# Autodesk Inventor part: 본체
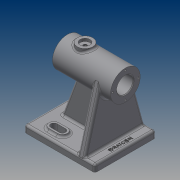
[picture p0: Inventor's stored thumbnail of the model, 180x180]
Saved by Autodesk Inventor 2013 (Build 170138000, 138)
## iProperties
Created: 2019-10
Part Number: 본체
Material: Generic
Document SubType Name: Modeling
Designer: user
Density: 1 g/cm^3
Author: user
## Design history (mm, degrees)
sketch "스케치1"
  geometry: L1 (-25, 0)-(57, 0); L2 (-25, 0)-(-25, 21); L3 (-25, 21)-(57, 21); L4 (-25, 0)-(-25, 14.5); L5 (-25, 14.5)-(37, 14.5); L6 (37, 14.5)-(37, 11.5); L7 (57, 21)-(57, 0); L8 (37, 11.5)-(57, 11.5); 1 further point
  constraints: 16 end point, 5 perpendicular, 3 point on line, 1 horizontal
  dimensions: "d0" = 82 distance of L1.start L1.end; "d1" = 25 distance of point (0, 0) L1.start; "d3" = 82 distance of L2.end L3.end; "d5" = 42 diameter of L3 L1; "d10" = 29 diameter of L5 L1; "d11" = 62 distance between parallel lines of L2 L6; "d12" = 23 diameter of L6.end L1
revolve "회전1" sketch "스케치1" stored, may be unused: angle "d13" = 90 deg
node "작업 평면1"
sketch "스케치2"
  geometry: L1 (-57, 21)-(-57, -21) reference; L2 (-57, -43)-(43, -43); L3 (43, -43)-(43, 43); L4 (43, 43)-(-57, 43); L5 (-57, 43)-(-57, -43); L6 (-57, -43)-(43, 43); L7 (43, -43)-(-57, 43); 3 further points
  constraints: 12 end point, 4 midpoint, 2 parallel, 1 horizontal, 1 perpendicular
  dimensions: "d15" = 100 distance of L4.end L3.end; "d16" = 86 distance of L3.end L2.end
extrude "돌출1" join sketch "스케치2" distance "d17" = 10; taper "d18" = 0 deg
fillet "모깎기1" dims "d19" = 3
sketch "스케치4"
  geometry: L1 (-43, 40)-(-43, -40) reference; L2 (57, -40)-(57, 40) reference; L3 (54, 43)-(-40, 43) reference; L4 (57, 0)-(42, 0); L5 (-43, 0)-(-28, 0); L6 (7, -5)-(42, -5); L7 (42, -5)-(42, 5); L8 (42, 5)-(7, 5); L9 (7, 5)-(7, -5); 1 further point
  constraints: 12 end point, 3 midpoint, 3 parallel, 1 collinear, 1 horizontal, 1 perpendicular
  dimensions: "d26" = 15 distance of L4.end L4.start; "d27" = 15 distance of L5.start L5.end; "d28" = 35 distance of L8.end L7.end; "d29" = 10 distance of L7.end L6.end
extrude "돌출3" join sketch "스케치4" stored distance "d30" = 10; taper "d31" = 0 deg
sketch "스케치5"
  geometry: L1 (37, -11.5)-(57, -11.5) reference; L2 (57, -11.5)-(57, -21) reference; L3 (57, -21)-(42, -21) reference; L4 (42, -21)-(42, -76) reference; L5 (42, -76)-(57, -76) reference; L6 (57, -76)-(57, -86) reference; L7 (57, -86)-(-43, -86) reference; L8 (-43, -86)-(-43, -76) reference; L9 (-43, -76)-(7, -76) reference; L10 (7, -76)-(7, -21) reference; L11 (7, -21)-(-25, -21) reference; L12 (-25, -21)-(-25, -14.5) reference; L13 (-25, -14.5)-(37, -14.5) reference; L14 (37, -14.5)-(37, -11.5) reference; L15 (-25, 21)-(57, 21) reference; L16 (57, 21)-(57, 11.5) reference; L17 (57, 11.5)-(37, 11.5) reference; L18 (37, 11.5)-(37, 14.5) reference; L19 (37, 14.5)-(-25, 14.5) reference; L20 (-25, 14.5)-(-25, 21) reference; L21 (-28, -76)-(-7.982, -21); 1 further point
  constraints: 2 end point, 2 point on line
  dimensions: "d32" = 15 distance of L21.start L8.end; "d33" = 70 deg angle of L9 L21
feature "리브1" sketch "스케치5" dims "d34" = 1, "d35" = 10, "d36" = 0, "d37" = 0, "d38" = 1, "d39" = 1
node "작업 평면2"
fillet "모깎기3" dims "d41" = 3
sketch "스케치6"
  geometry: L1 (83, 7)-(83, 0) reference; L2 (83, 0)-(-3, 0) reference; L3 (-3, 0)-(-3, 7) reference; L4 (0, 10)-(35, 10) reference; L5 (35, 10)-(35, 65.604) reference; L6 (45, 65.604)-(45, 10) reference; L7 (45, 10)-(80, 10) reference; L8 (-3, 7)-(19.721, 91.456); L9 (83, 7)-(60.279, 91.456); C1 r 14.5 at (40, 86) reference; C2 r 11.5 at (40, 86) reference; A1 r 3 centre (80, 7) between (83, 7) and (80, 10) reference; A2 r 3 centre (0, 7) between (0, 10) and (-3, 7) reference; A3 r 21 centre (40, 86) between (45, 65.604) and (35, 65.604) reference; 1 further point
  constraints: 4 end point, 2 point on circle, 2 tangent
extrude "돌출4" join sketch "스케치6" stored distance "d42" = 10; taper "d43" = 0 deg
fillet "모깎기4" dims "d44" = 3
fillet "모깎기5" dims "d45" = 3
sketch "스케치7"
  geometry: L1 (0, 0)-(0, 18); C1 r 21 at (0, 0) reference; 1 further point
  constraints: 2 end point, 1 coincident, 1 vertical
  dimensions: "d46" = 18 distance of L1.start L1.end
hole "구멍1" sketch "스케치7" at (0, 18) diameter "d47" = 2.459; stored, may be unused: countersink angle "d51" = 90 deg, drill point angle "d53" = 118 deg; dims "d48" = 8, "d49" = 4, "d50" = 2, "d52" = 10
sketch "스케치8"
  geometry: L1 (0, 0)-(0, 18); C1 r 14.5 at (0, 0) reference; 1 further point
  constraints: 2 end point, 1 coincident, 1 vertical
  dimensions: "d57" = 18 distance of L1.start L1.end
hole "구멍2" sketch "스케치8" at (0, 18) diameter "d58" = 2.459; stored, may be unused: countersink angle "d62" = 90 deg, drill point angle "d64" = 118 deg; dims "d59" = 8, "d60" = 4, "d61" = 2, "d63" = 10
chamfer "모따기1" distance "d68" = 1; stored, may be unused: second distance "d69" = 2, angle "d70" = 45 deg
sketch "스케치9"
  geometry: L1 (-30.101, 2)-(-30.101, -2) reference; L2 (-43, 40)-(-43, -40) reference; L3 (-43, 0)-(-30.101, 0); L4 (-43, 0)-(-43, 27); L5 (-43, 27)-(-17, 27); L6 (-17, 34)-(-5, 34); L7 (-5, 34)-(-5, 20); L8 (-5, 20)-(-17, 20); L9 (-17, 20)-(-17, 34); 3 further points
  constraints: 14 end point, 4 midpoint, 2 parallel, 2 perpendicular, 2 vertical alignment, 1 coincident, 1 horizontal, 1 point on line, 4 other
  dimensions: "d74" = 27 distance of L3.start L4.end; "d76" = 26 distance of L5.end L4.end; "d77" = 12 distance of L7.end L8.end; "d78" = 14 distance of L6.end L7.end
extrude "돌출5" join sketch "스케치9" distance "d79" = 3; taper "d80" = 0 deg
sketch "스케치10"
  geometry: L1 (-17, 31.5)-(-5, 31.5); L2 (-17, 22.5)-(-5, 22.5); A1 r 7 centre (-5, 27) between (-5, 20) and (-5, 34) reference; A2 r 7 centre (-17, 27) between (-17, 34) and (-17, 20) reference; A3 r 4.5 centre (-17, 27) between (-17, 31.5) and (-17, 22.5); A4 r 4.5 centre (-5, 27) between (-5, 31.5) and (-5, 22.5); 1 further point
  constraints: 4 end point, 4 point on circle, 4 tangent, 2 centre point, 2 coincident
  dimensions: "d81" = 9 diameter of A3; "d82" = 9 diameter of A4
extrude "돌출6" cut sketch "스케치10" stored distance "d83" = 0; taper "d84" = 0 deg
fillet "모깎기6" dims "d85" = 3
node "작업 평면3"
sketch "스케치11"
  geometry: C1 r 11 at (0, 0); 1 further point
  constraints: 1 centre point, 1 coincident
  dimensions: "d87" = 22 diameter of C1
extrude "돌출7" join sketch "스케치11" stored distance "d88" = 3; taper "d89" = 0 deg
sketch "스케치12"
  geometry: C1 r 11 at (0, 0) reference; C2 r 7 at (0, 0)
  constraints: 1 centre point, 1 coincident
  dimensions: "d90" = 14 diameter of C2
extrude "돌출8" cut sketch "스케치12" distance "d91" = 4; taper "d92" = 0 deg
sketch "스케치13"
  geometry: C1 r 7 at (0, 0) reference; 1 further point
  constraints: 1 coincident
hole "구멍3" sketch "스케치13" at (0, 0) diameter "d93" = 4.917; stored, may be unused: countersink angle "d97" = 90 deg, drill point angle "d99" = 118 deg; dims "d94" = 8, "d95" = 4, "d96" = 2, "d98" = 10
fillet "모깎기7" dims "d100" = 3
sketch "스케치14"
  geometry: L1 (57, -40)-(57, 40) reference; 3 further points
  constraints: 1 horizontal alignment, 1 midpoint, 1 other
  dimensions: "d101" = 7 distance from line of L1 point (50, 0)
feature "엠보싱1" sketch "스케치14" dims "d102" = 0.5, "d103" = 0
node "솔리드1"
pattern_circular "원형 패턴1" dims angle "d55" = 360 deg
pattern_circular "원형 패턴2" dims angle "d66" = 360 deg
mirror "대칭1"
node "절단 모서리 투영1"
node "절단 모서리 투영2"
other parameters: "d14" = -86, "d86" = 24
